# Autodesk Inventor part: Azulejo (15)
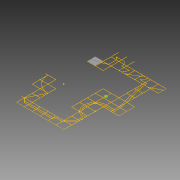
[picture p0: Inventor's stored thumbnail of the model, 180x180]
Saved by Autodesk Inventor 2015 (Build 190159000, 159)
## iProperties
Created: 2015-04
Part Number: Azulejo (15)
Material: Genérico
Document SubType Name: Modeling
Designer: Felipe
Density: 1 g/cm^3
Appearance: Padrão
Author: Felipe
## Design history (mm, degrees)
sketch "Sketch1"
  geometry: L1 (-1510, -7490)-(-1510, -6010); L2 (992.445, 7510)-(992.445, 8990); L3 (1012.445, 7510)-(1012.445, 8990); L4 (-3010, -1490)-(-3010, -10); L5 (-2990, 10)-(-1510, 10); L6 (-1510, -10)-(-2990, -10); L7 (-1510, -1490)-(-1510, -10); L8 (-10, 9010)-(-10, 10490); L9 (-10, 7510)-(-10, 8990); L10 (-10, 7490)-(-1490, 7490); L11 (-1490, 6010)-(-10, 6010); L12 (-10, 5990)-(-1490, 5990); L13 (-1490, -10)-(-1490, -1490); L14 (-1490, -1490)-(-10, -1490); L15 (-10, -1510)-(-1490, -1510); L16 (-10, -2990)-(-10, -1510); L17 (-10, -5990)-(-10, -4510); L18 (-1490, -7490)-(-10, -7490); L19 (10, 8990)-(10, 7510); L20 (1490, 7510)-(1490, 8990); L21 (10, 6010)-(1490, 6010); L22 (1490, 6010)-(1490, 7490); L23 (1490, 5990)-(10, 5990); L24 (4490, -6010)-(3010, -6010); L25 (10, -1510)-(10, -2990); L26 (10, -3010)-(10, -4490); L27 (10, -4510)-(10, -5990); L28 (10, -5990)-(1490, -5990); L29 (1490, -6010)-(10, -6010); L30 (10, -7490)-(1490, -7490); L31 (2990, 9010)-(2990, 10490); L32 (1510, 8990)-(1510, 7510); L33 (1510, 7510)-(2990, 7510); L34 (2990, 7490)-(1510, 7490); L35 (1510, 7490)-(1510, 6010); L36 (1510, -5990)-(2990, -5990); L37 (2990, -6010)-(1510, -6010); L38 (1510, -7490)-(2990, -7490); L39 (3010, 10490)-(3010, 9010); L40 (3010, 9010)-(4490, 9010); L41 (4490, 8990)-(3010, 8990); L42 (4490, 7490)-(3010, 7490); L43 (4490, 1510)-(4490, 2990); L44 (4490, 10)-(4490, 1490); L45 (4490, -1490)-(4490, -10); L46 (4490, -2990)-(4490, -1510); L47 (3010, -5990)-(4490, -5990); L48 (3010, -7490)-(4490, -7490); L49 (4510, 9010)-(5990, 9010); L50 (5990, 8990)-(4510, 8990); L51 (4510, 7510)-(5990, 7510); L52 (5990, 7490)-(4510, 7490); L53 (4510, 3010)-(5990, 3010); L54 (5990, 2990)-(4510, 2990); L55 (4510, 2990)-(4510, 1510); L56 (4510, 1510)-(5990, 1510); L57 (5990, 1510)-(5990, 1740.185); L58 (5990, 1760.2)-(5990, 2259.8); L59 (5990, 2279.815)-(5990, 2990); L60 (5990, 1490)-(4510, 1490); L61 (4510, 1490)-(4510, 10); L62 (4510, 10)-(5990, 10); L63 (5990, 10)-(5990, 1490); L64 (5975.983, -10)-(4510, -10)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; A1 r 250 centre (6000, 2010) between (5990, 2259.8) and (5990, 1760.2); A2 r 250 centre (6000, 2010) between (6010, 1760.2) and (6010, 2259.8); A3 r 270 centre (6000, 2010) between (5990, 2279.815) and (5990, 1740.185); A4 r 270 centre (6000, 2010) between (6010, 1740.185) and (6010, 2279.815); A5 r 3010.017 centre (0, 0) between (-1490, -2615.358) and (-346.554, -2990); A6 r 2990.017 centre (0, 0) between (-1490, -2592.316) and (-10, -2990); A7 r 3010.017 centre (0, 0) between (-2603.863, -1510) and (-1510, -2603.863); A8 r 2990.017 centre (0, 0) between (-2580.717, -1510) and (-1510, -2580.717); A9 r 3010.017 centre (0, 0) between (-2990, -346.554) and (-2615.358, -1490); A10 r 2990.017 centre (0, 0) between (-2990, -10) and (-2592.316, -1490); A11 r 2131.367 centre (7500, -1500) between (7490, 631.344) and (6010, 24.017); A12 r 2131.367 centre (7500, -1500) between (5975.983, -10) and (5368.656, -1490); A13 r 2131.367 centre (7500, -1500) between (5368.656, -1510) and (5975.983, -2990); A14 r 2131.367 centre (7500, -1500) between (6010, -3024.017) and (7190, -3608.703); A15 r 1831.367 centre (7500, -1500) between (7490.321, 331.342) and (6463.753, 10); A16 r 1831.367 centre (7500, -1500) between (6435.196, -10) and (6010, -435.196); A17 r 1831.367 centre (7500, -1500) between (5990, -463.753) and (5668.66, -1490); A18 r 1831.367 centre (7500, -1500) between (5668.66, -1510) and (5990, -2536.247); A19 r 1831.367 centre (7500, -1500) between (6010, -2564.804) and (6435.196, -2990); A20 r 1831.367 centre (7500, -1500) between (6463.753, -3010) and (7490, -3331.34); A21 r 2111.367 centre (7500, -1500) between (7490.047, 611.344) and (6024.272, 10); A22 r 2111.367 centre (7500, -1500) between (5990, -24.272) and (5388.656, -1490); A23 r 2111.367 centre (7500, -1500) between (5388.656, -1510) and (5990, -2975.728); A24 r 2111.367 centre (7500, -1500) between (6024.272, -3010) and (7210, -3591.357); A25 r 1811.367 centre (7500, -1500) between (7490.374, 311.342) and (6499.524, 10); A26 r 1811.367 centre (7500, -1500) between (6469.975, -10) and (6010, -469.975); A27 r 1811.367 centre (7500, -1500) between (5990, -499.524) and (5688.66, -1490); A28 r 1811.367 centre (7500, -1500) between (5688.66, -1510) and (5990, -2500.476); A29 r 1811.367 centre (7500, -1500) between (6010, -2530.025) and (6469.975, -2990); A30 r 1811.367 centre (7500, -1500) between (6499.524, -3010) and (7490, -3311.34); A31 r 449.871 centre (7499.449, -4060.672) between (7510, -4510.419) and (7521.546, -4510); 4 further points
  constraints: 1014 end point, 64 point on circle, 31 centre point, 13 point on line, 1 other
extrude "Extrusion1" new body sketch "Sketch1" distance "d0" = 60; taper "d1" = 0 deg
extrude "Extrusion2" new body sketch "Sketch1" distance "d2" = 60; taper "d3" = 0 deg
body "Solid1"
body "Solid2"
